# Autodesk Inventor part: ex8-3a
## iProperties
Author: Administrator
Created: 2001-03
Part Number: ex8-3a
Document SubType Name: Modeling
Designer: Administrator
Control State: 0
Master: False
Checked Out: False
PropertySet Name: Design Tracking Control
Shininess: 20.0
PropertySet Name: _Private Model Information
Density: 0.0
Volumn: 0.0
Area: 0.0
PropertySet Name: Model Information
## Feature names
1. Extrusion1
2. Extrusion2
